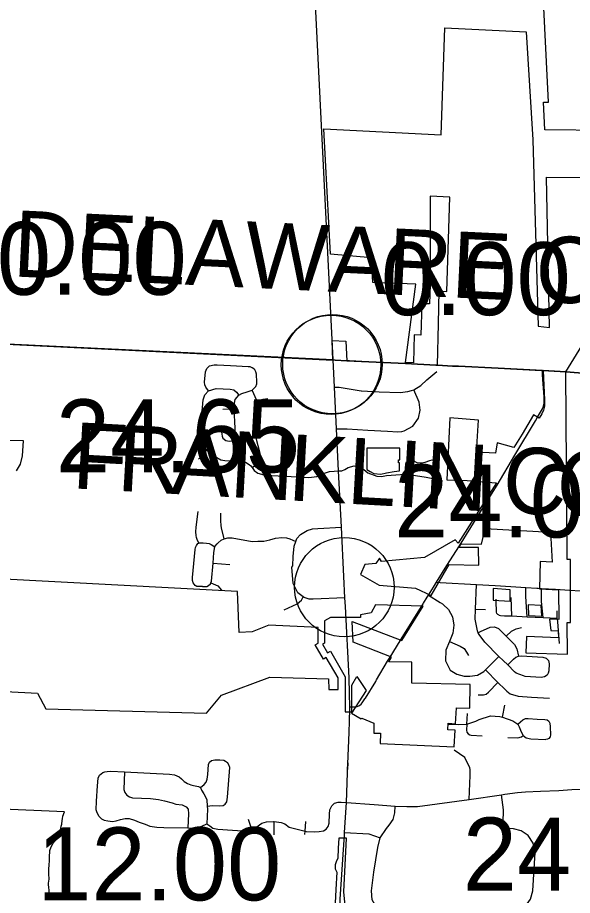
# Model space of a CAD drawing. Extents: x 1729596 to 1934326, y 644115 to 911751.
# Drawn here: x 1819179 to 1827541, y 770599 to 783844 of the extents above; entities that cross this region are included whole.
import ezdxf

# ---------------------------------------------------------------- set-up
doc = ezdxf.new("R2010")
doc.units = 0
for name, color, linetype in [('Default', 7, 'Continuous'), ('GM_X_Adjacent_County_Text', 7, 'Continuous'), ('GM_X_City_Street', 7, 'Continuous'), ('GM_X_Corporation', 7, 'Continuous'), ('GM_X_County', 7, 'Continuous'), ('GM_X_County_Road', 7, 'Continuous'), ('GM_X_Township_Road', 7, 'Continuous'), ('GM_X_US_Route', 7, 'Continuous')]:
    doc.layers.add(name, color=color, linetype=linetype)

msp = doc.modelspace()

# ---------------------------------------------------------------- linework, layer by layer
at = {"layer": 'Default'}
for centre in [(1823904, 778604), (1823904, 778604), (1823925, 778615), (1824103, 775250)]:
    msp.add_circle(centre, 750, dxfattribs=at)
at = {"layer": 'GM_X_City_Street'}
for points in [[(1827440, 778500), (1827802, 779087), (1828113, 779577), (1828183, 779692), (1828216, 779780), (1828313, 780101), (1828381, 780311), (1828487, 780643), (1828494, 780666)], [(1823936, 778682), (1823966, 778677), (1824141, 778666), (1824146, 778666)], [(1823936, 778682), (1823966, 778677), (1824145, 778671)], [(1822056, 778210), (1822017, 778267), (1821999, 778304), (1821997, 778344), (1822012, 778499), (1822031, 778551), (1822071, 778589), (1822141, 778605), (1822189, 778603), (1822388, 778593), (1822653, 778580), (1822678, 778578), (1822720, 778561)], [(1822459, 777154), (1822464, 777254), (1822464, 777456), (1822465, 777499), (1822458, 777648), (1822445, 777941), (1822443, 777995), (1822460, 778079), (1822513, 778146), (1822561, 778171), (1822637, 778197), (1822717, 778224), (1822770, 778277), (1822785, 778317), (1822786, 778344), (1822778, 778462), (1822771, 778498), (1822754, 778530), (1822720, 778561)], [(1824146, 778666), (1825025, 778622), (1825481, 778599), (1825506, 778597), (1825514, 778597)], [(1825505, 778597), (1825506, 778597), (1825736, 778586), (1825825, 778586), (1826422, 778555), (1827074, 778521)], [(1825514, 778597), (1825736, 778586), (1825825, 778586), (1826422, 778555), (1827092, 778520)], [(1824361, 778210), (1824631, 778199), (1824945, 778189), (1825060, 778201), (1825118, 778217), (1825151, 778228), (1825258, 778295), (1825347, 778377), (1825499, 778503)], [(1826983, 777761), (1827016, 777817), (1827089, 777940), (1827102, 777967), (1827111, 777999), (1827114, 778033), (1827114, 778068), (1827113, 778120), (1827100, 778318), (1827091, 778452), (1827091, 778494), (1827092, 778520)], [(1827074, 778521), (1827092, 778520), (1827440, 778500)], [(1827092, 778520), (1827440, 778500), (1827460, 778499)], [(1827440, 778500), (1827947, 778461), (1830173, 778324)], [(1827460, 778499), (1827947, 778461), (1830193, 778323)], [(1822030, 777316), (1821996, 777351), (1821952, 777420), (1821932, 777499), (1821933, 777562), (1821957, 777843), (1821975, 778075), (1822002, 778151), (1822056, 778210), (1822172, 778248), (1822383, 778239), (1822436, 778227), (1822477, 778194), (1822513, 778146)], [(1822716, 777056), (1822751, 777079), (1822801, 777116), (1822834, 777160), (1822843, 777198), (1822840, 777237), (1822833, 777267), (1822773, 777498), (1822769, 777583), (1822782, 777791), (1822794, 777953), (1822786, 778068), (1822717, 778224)], [(1823953, 778265), (1824024, 778269), (1824205, 778239), (1824356, 778210), (1824361, 778210)], [(1823985, 777638), (1824147, 777638), (1824458, 777620), (1824752, 777603), (1824912, 777595), (1824968, 777601), (1825006, 777608), (1825135, 777678), (1825221, 777798), (1825249, 777919), (1825232, 778042), (1825151, 778228)], [(1822786, 778068), (1822830, 778076), (1822876, 778087), (1822951, 778097)], [(1822273, 777933), (1822445, 777941)], [(1822253, 777594), (1822255, 777556), (1822260, 777526), (1822274, 777498), (1822318, 777462), (1822369, 777454), (1822464, 777456)], [(1821905, 777183), (1822030, 777316)], [(1822030, 777316), (1822105, 777249), (1822156, 777220)], [(1822156, 777220), (1822240, 777172), (1822304, 777161), (1822459, 777154), (1822535, 777147), (1822555, 777146), (1822616, 777134), (1822670, 777102), (1822692, 777082), (1822716, 777056), (1822747, 777008), (1822799, 776968), (1822889, 776943), (1823010, 776935), (1823496, 776909), (1823569, 776903), (1823690, 776921), (1823734, 776940), (1823773, 776959), (1823881, 776995), (1823951, 777001), (1824018, 777004)], [(1824018, 777004), (1824065, 777007), (1824109, 777025), (1824161, 777054), (1824251, 777080), (1824358, 777055), (1824400, 777025), (1824459, 776977), (1824592, 776923), (1824663, 776922), (1824740, 776933), (1825018, 776954), (1825175, 776934), (1825336, 776910), (1825435, 776889)], [(1825018, 776954), (1825031, 777112), (1825042, 777142), (1825065, 777164), (1825087, 777174), (1825110, 777175), (1825144, 777161), (1825168, 777146), (1825197, 777133), (1825274, 777125), (1825322, 777138), (1825390, 777163), (1825427, 777169), (1825464, 777164), (1825508, 777129), (1825524, 777096), (1825526, 777059), (1825519, 777020), (1825484, 776879)], [(1825435, 776889), (1825484, 776879), (1825584, 776853)], [(1821913, 775914), (1821888, 775969), (1821876, 776000), (1821869, 776029), (1821865, 776086), (1821868, 776154), (1821900, 776394)], [(1822295, 775980), (1822252, 776143), (1822245, 776179), (1822240, 776252), (1822243, 776366)], [(1824113, 775091), (1823635, 775067), (1823574, 775071), (1823496, 775095), (1823484, 775103), (1823404, 775164), (1823334, 775303), (1823314, 775554), (1823326, 775574), (1823334, 775711), (1823349, 775867), (1823374, 775941), (1823389, 775982), (1823445, 776047), (1823541, 776103), (1823626, 776131), (1823704, 776136), (1824060, 776153)], [(1821966, 775258), (1821883, 775258), (1821853, 775273), (1821838, 775294), (1821826, 775316), (1821815, 775353), (1821815, 775395), (1821853, 775817), (1821862, 775849), (1821876, 775881), (1821896, 775908), (1821913, 775914), (1821928, 775918), (1821976, 775917), (1822027, 775912), (1822064, 775907), (1822098, 775892), (1822152, 775856)], [(1821966, 775258), (1822029, 775262), (1822057, 775274), (1822085, 775300), (1822093, 775316), (1822104, 775339), (1822125, 775611), (1822138, 775775), (1822152, 775856), (1822153, 775862), (1822187, 775906), (1822200, 775917), (1822201, 775918)], [(1822201, 775918), (1822249, 775961), (1822290, 775979), (1822295, 775980), (1822347, 775993), (1822415, 775993), (1822715, 775941), (1822802, 775943), (1822891, 775946), (1822982, 775965), (1823068, 775990), (1823161, 776001), (1823234, 775995), (1823282, 775981), (1823374, 775941)], [(1822125, 775611), (1822379, 775591)], [(1822093, 775316), (1822198, 775270), (1822253, 775203)], [(1825495, 775326), (1825549, 775321), (1826095, 775288), (1826379, 775273), (1826611, 775259), (1826837, 775246), (1827003, 775237), (1827023, 775235)], [(1826802, 773912), (1826692, 773954), (1826668, 773975), (1826566, 774077), (1826497, 774144), (1826434, 774206), (1826220, 774418), (1826134, 774536), (1826121, 774563), (1826109, 774591), (1826076, 774769), (1826083, 774917), (1826095, 775288)], [(1826858, 774804), (1826848, 774951), (1826840, 775111), (1826837, 775246)], [(1827099, 774790), (1827075, 775036), (1827076, 775232)], [(1823197, 774908), (1823394, 774998), (1823460, 775055), (1823484, 775103)], [(1825296, 775010), (1825353, 775100)], [(1825373, 775131), (1825548, 775021), (1825581, 774998), (1825593, 774987)], [(1826628, 774818), (1826617, 775093)], [(1827498, 775207), (1827662, 775197), (1828600, 775146), (1828663, 775145), (1828778, 775136), (1829364, 775096), (1829531, 775087), (1830387, 775031), (1831077, 774994), (1831207, 774985), (1832172, 774932), (1832553, 774913), (1832991, 774890), (1833285, 774873), (1833579, 774858), (1833879, 774836), (1833947, 774835), (1833997, 774825), (1834053, 774805), (1834088, 774789), (1834140, 774757), (1834272, 774660), (1834319, 774634)], [(1825593, 774987), (1825674, 774913), (1825734, 774802), (1825756, 774679), (1825740, 774556), (1825691, 774428), (1825635, 774300), (1825627, 774140), (1825701, 773998), (1825797, 773936), (1825908, 773909), (1825995, 773905), (1826109, 773922), (1826207, 773979), (1826232, 774002), (1826434, 774206)], [(1826435, 774829), (1826416, 774836), (1826401, 774853), (1826396, 774871), (1826395, 774911), (1826393, 774998), (1826391, 775067)], [(1826083, 774917), (1826229, 774912)], [(1826435, 774829), (1826458, 774824), (1826516, 774818), (1826628, 774818), (1826858, 774804), (1827099, 774790), (1827311, 774780)], [(1827323, 774727), (1827323, 774736), (1827311, 774780), (1827313, 774834), (1827310, 774891)], [(1827349, 774398), (1827323, 774727)], [(1826121, 774563), (1826158, 774582), (1826301, 774645), (1826366, 774653), (1826425, 774625), (1826545, 774510), (1826669, 774386), (1826704, 774322), (1826727, 774209)], [(1826545, 774510), (1826622, 774587), (1826693, 774621), (1826775, 774640)], [(1824792, 774194), (1824943, 774438), (1824960, 774466)], [(1825691, 774428), (1825851, 774360), (1825908, 774324), (1825946, 774268), (1825976, 774220)], [(1826566, 774077), (1826653, 774166), (1826687, 774193), (1826727, 774209), (1826772, 774213), (1827096, 774194), (1827145, 774180), (1827180, 774142), (1827190, 774092), (1827185, 773986), (1827178, 773952), (1827160, 773923)], [(1826232, 774002), (1826419, 773811), (1826523, 773711), (1826552, 773682), (1826605, 773642), (1826725, 773604), (1826925, 773592), (1827194, 773577)], [(1827160, 773923), (1827119, 773896), (1827071, 773889), (1826828, 773903), (1826802, 773912)], [(1824420, 773573), (1824421, 773575), (1824576, 773829), (1824582, 773839), (1824583, 773841)], [(1826119, 773628), (1826202, 773628), (1826242, 773638), (1826274, 773665), (1826419, 773811)], [(1824241, 773445), (1824265, 773445), (1824298, 773448), (1824324, 773460), (1824355, 773485), (1824357, 773487)], [(1826486, 773291), (1826525, 773472)], [(1825670, 773185), (1825820, 773176), (1825950, 773184), (1825996, 773196), (1826084, 773229), (1826134, 773255), (1826307, 773307), (1826445, 773298), (1826486, 773291), (1826641, 773232), (1826717, 773181), (1826737, 773144), (1826767, 773067), (1826797, 773010), (1826846, 772978), (1826915, 772963), (1827142, 772952)], [(1825950, 773184), (1825960, 773342)], [(1826717, 773181), (1826757, 773218), (1826794, 773249), (1826832, 773266), (1826874, 773269), (1827008, 773260), (1827128, 773254), (1827160, 773246), (1827185, 773227), (1827199, 773198), (1827205, 773143), (1827211, 773023), (1827204, 772993), (1827187, 772969), (1827166, 772956), (1827142, 772952)], [(1825950, 773184), (1825945, 773090), (1825952, 773061), (1825970, 773036), (1825996, 773021), (1826014, 773018), (1826181, 773007)], [(1826566, 772981), (1826721, 772975), (1826774, 772992), (1826797, 773010)], [(1825983, 772046), (1825999, 772408), (1826001, 772438), (1826001, 772498), (1825996, 772523), (1825922, 772681), (1825761, 772791)], [(1821936, 772229), (1821990, 772275), (1822020, 772310), (1822038, 772355), (1822047, 772422), (1822056, 772574), (1822072, 772610), (1822104, 772635), (1822154, 772645), (1822229, 772644), (1822288, 772638), (1822315, 772627), (1822341, 772604)], [(1822037, 771947), (1822119, 771954), (1822222, 771949), (1822279, 771954), (1822309, 771978), (1822334, 772011), (1822342, 772080), (1822377, 772528), (1822362, 772570), (1822341, 772604)], [(1820406, 771790), (1820378, 771847), (1820361, 771892), (1820368, 772023), (1820384, 772253), (1820393, 772369), (1820415, 772414), (1820464, 772453)], [(1820464, 772453), (1820492, 772463), (1820529, 772470), (1820583, 772472), (1820792, 772462), (1821467, 772429), (1821543, 772419), (1821614, 772390), (1821650, 772357), (1821690, 772320), (1821742, 772286), (1821790, 772268), (1821830, 772257), (1821907, 772243), (1821936, 772229), (1821952, 772186), (1821987, 772131), (1822009, 772087), (1822031, 772040), (1822037, 771947), (1822039, 771901), (1822032, 771679)], [(1820792, 772462), (1820781, 772195), (1820796, 772150), (1820826, 772112), (1820866, 772089), (1820913, 772073), (1821180, 772064), (1821302, 772045), (1821395, 772025), (1821510, 771996), (1821566, 771977), (1821660, 771966), (1821721, 771937), (1821748, 771901), (1821757, 771828), (1821747, 771618)], [(1826525, 772125), (1826714, 772151), (1826836, 772161), (1827059, 772170), (1827337, 772184), (1827532, 772195), (1827691, 772201), (1828033, 772218), (1828183, 772224), (1828323, 772224), (1828435, 772215), (1828494, 772212), (1828931, 772182), (1829307, 772160), (1829765, 772135), (1829929, 772122)], [(1824135, 772002), (1824551, 771970), (1824871, 771948), (1825045, 771940), (1825204, 771941), (1825983, 772046), (1826472, 772117), (1826525, 772125)], [(1826492, 771616), (1826504, 771852), (1826502, 771888), (1826472, 772117)], [(1822032, 771679), (1822074, 771650), (1822123, 771615), (1822197, 771601), (1822638, 771569), (1822714, 771577), (1822771, 771622), (1822860, 771691), (1822929, 771707), (1823035, 771715), (1823046, 771714), (1823151, 771697), (1823206, 771680), (1823271, 771631), (1823513, 771567), (1823526, 771564), (1823659, 771561), (1823724, 771563), (1823792, 771576), (1823832, 771598), (1823860, 771639), (1823875, 771688), (1823879, 771823), (1823887, 771892), (1823913, 771949), (1823955, 771990), (1824010, 772008), (1824057, 772005), (1824135, 772002)], [(1824644, 770369), (1824587, 770417), (1824524, 770534), (1824512, 770667), (1824546, 770950), (1824608, 771322), (1824643, 771469), (1824738, 771611), (1824779, 771657), (1824839, 771744), (1824865, 771846), (1824871, 771948)], [(1820406, 771790), (1820446, 771755), (1820483, 771736), (1820541, 771727), (1820611, 771712), (1820665, 771727), (1820728, 771746), (1820798, 771762), (1820862, 771759), (1820939, 771736), (1821011, 771704), (1821102, 771676), (1821172, 771643), (1821279, 771631), (1821385, 771623), (1821747, 771618), (1821837, 771616), (1821899, 771625), (1821956, 771644), (1822032, 771679)], [(1822714, 771577), (1822658, 771747)], [(1823047, 771513), (1823046, 771714)], [(1823509, 771520), (1823513, 771567), (1823525, 771712)], [(1824106, 771550), (1824475, 771530), (1824643, 771469)], [(1826832, 770435), (1826910, 770542), (1826947, 770669), (1826978, 771246), (1826951, 771386), (1826872, 771504), (1826771, 771573), (1826654, 771605), (1826555, 771611), (1826492, 771616)]]:
    msp.add_lwpolyline(points, dxfattribs=at)
at = {"layer": 'GM_X_Corporation'}
for points in [[(1829006, 782129), (1827128, 782148), (1827107, 782565), (1827182, 782566), (1827094, 784298)], [(1818182, 778957), (1823932, 778674), (1823918, 778971), (1824127, 778960), (1824141, 778666), (1825025, 778622), (1825481, 778599), (1825506, 778597), (1825523, 779224), (1825533, 779720), (1825651, 779713), (1825692, 781132), (1825397, 781147), (1825395, 779815), (1825387, 779525), (1825271, 779527), (1825258, 779053), (1825157, 779059), (1825145, 778634), (1825026, 778639), (1825182, 779821), (1824534, 779849), (1824515, 780220), (1823897, 780274), (1823795, 782165), (1825564, 782072), (1825620, 783690), (1826843, 783626), (1826946, 782000), (1827027, 779186), (1827198, 779170), (1827151, 781435), (1828757, 781433)], [(1819165, 777003), (1819223, 777108), (1819253, 777229), (1819268, 777456), (1818703, 777466)], [(1818508, 773703), (1819478, 773652), (1819605, 773412), (1822027, 773351), (1822253, 773619), (1822982, 773891), (1823867, 773865), (1823869, 773706), (1824013, 773704), (1824009, 773883), (1823832, 774190), (1823788, 774165), (1823663, 774381), (1823707, 774406), (1823707, 774642), (1822967, 774677), (1822717, 774575), (1822517, 774567), (1822492, 775187), (1818880, 775374)], [(1819656, 770583), (1819656, 770666), (1819650, 770728), (1819647, 770756), (1819647, 770786), (1819650, 770814), (1819656, 770842), (1819656, 770870), (1819650, 770898), (1819650, 770984), (1819650, 771015), (1819653, 771043), (1819656, 771074), (1819662, 771108), (1819662, 771166), (1819659, 771194), (1819665, 771250), (1819665, 771278), (1819684, 771333), (1819714, 771389), (1819742, 771417), (1819767, 771445), (1819779, 771472), (1819795, 771500), (1819807, 771528), (1819820, 771584), (1819829, 771611), (1819838, 771645), (1819844, 771673), (1819850, 771729), (1819857, 771757), (1819863, 771794), (1819885, 771859), (1818834, 771906)], [(1824115, 770445), (1824097, 770653), (1824134, 771461), (1824020, 771463), (1824012, 771314), (1824004, 771157), (1823985, 771119), (1823963, 771063), (1823967, 770998), (1823992, 770950), (1823977, 770688), (1823965, 770484)]]:
    msp.add_lwpolyline(points, dxfattribs=at)
for points in [[(1824345, 775442), (1824627, 775281), (1825175, 775235), (1825413, 775126), (1825685, 775591), (1826129, 775580), (1826126, 775849), (1825830, 775846), (1825867, 775906), (1826173, 775897), (1826228, 776137), (1827210, 776079), (1827238, 775627), (1827055, 775635), (1827043, 775226), (1827330, 775211), (1827337, 774761), (1827196, 774766), (1827218, 774598), (1827327, 774593), (1827332, 774484), (1826851, 774504), (1826841, 774261), (1827466, 774237), (1827464, 774716), (1827514, 774716), (1827510, 775666), (1827460, 775665), (1827440, 778500), (1827098, 778520), (1827121, 778076), (1827120, 777980), (1827107, 777918), (1827081, 777867), (1827042, 777801), (1826956, 777852), (1826782, 777559), (1826660, 777355), (1826409, 777430), (1826380, 777271), (1826098, 777288), (1826124, 777772), (1825694, 777807), (1825650, 776871), (1826109, 776852), (1826109, 776842), (1826395, 776822), (1825819, 775914), (1825776, 775965), (1825313, 775697), (1824665, 775637), (1824635, 775689), (1824578, 775607), (1824414, 775592)], [(1824442, 777348), (1824442, 777026), (1824494, 776994), (1824548, 776966), (1824656, 776953), (1824740, 776974), (1824853, 776996), (1824934, 777003), (1824934, 777124), (1824922, 777124), (1824922, 777172), (1824942, 777172), (1824942, 777248), (1824942, 777348)], [(1826345, 775056), (1826603, 775041), (1826601, 775212), (1826347, 775231)], [(1823775, 774388), (1823850, 774258), (1823893, 774283), (1824116, 773897), (1824117, 773370), (1824217, 773370), (1824216, 773770), (1824292, 773900), (1824434, 773692), (1824210, 773349), (1824358, 773262), (1824368, 773274), (1824549, 773200), (1824547, 773047), (1824647, 773046), (1824645, 772890), (1825759, 772839), (1825774, 773090), (1825665, 773097), (1825671, 773197), (1825780, 773190), (1825795, 773428), (1825995, 773423), (1825999, 773780), (1825120, 773801), (1825121, 774119), (1824773, 774122), (1824817, 774196), (1824236, 774422), (1824220, 774734), (1824970, 774444), (1825290, 774965), (1824574, 774985), (1824507, 774863), (1824348, 774835), (1824349, 774792), (1823893, 774792), (1823807, 774742), (1823807, 774406)], [(1826873, 774982), (1826880, 774820), (1827079, 774810), (1827071, 774971)]]:
    msp.add_lwpolyline(points, close=True, dxfattribs=at)
at = {"layer": 'GM_X_County'}
for points in [[(1811853, 779256), (1817214, 778979), (1817250, 778977), (1818151, 778958), (1818187, 778957), (1823936, 778682), (1823966, 778677), (1824141, 778666), (1825025, 778622), (1825481, 778599), (1825506, 778597), (1825736, 778586), (1825825, 778586), (1826422, 778555), (1827092, 778520), (1827440, 778500), (1827947, 778461)], [(1827947, 778461), (1827440, 778500), (1827092, 778520), (1826422, 778555), (1825825, 778586), (1825736, 778586), (1825506, 778597), (1825481, 778599), (1825025, 778622), (1824141, 778666), (1823966, 778677), (1823936, 778682), (1818187, 778957), (1818151, 778958), (1817250, 778977), (1817214, 778979), (1811853, 779256)]]:
    msp.add_lwpolyline(points, dxfattribs=at)
at = {"layer": 'GM_X_County_Road'}
for points in [[(1825353, 775100), (1825373, 775131), (1825449, 775251), (1825495, 775326), (1825646, 775575), (1825837, 775875), (1826221, 776491), (1826407, 776790), (1826673, 777239), (1826983, 777761)], [(1827023, 775235), (1827076, 775232), (1827287, 775220), (1827498, 775207)], [(1824960, 774466), (1825290, 774999), (1825296, 775010)], [(1824589, 773850), (1824756, 774135), (1824792, 774194)], [(1824583, 773841), (1824588, 773850), (1824589, 773850)], [(1824357, 773487), (1824374, 773504), (1824415, 773565), (1824420, 773572), (1824420, 773573)], [(1824188, 773445), (1824241, 773445)]]:
    msp.add_lwpolyline(points, dxfattribs=at)
at = {"layer": 'GM_X_Township_Road'}
msp.add_lwpolyline([(1824145, 778671), (1824181, 778670), (1825025, 778622), (1825481, 778599), (1825505, 778597)], dxfattribs=at)
at = {"layer": 'GM_X_US_Route'}
for points in [[(1823936, 778682), (1823645, 784547), (1823597, 785555), (1823580, 785831), (1823563, 786025)], [(1824097, 775409), (1824060, 776153), (1824018, 777004), (1823985, 777638), (1823953, 778265), (1823936, 778682)], [(1824119, 774956), (1824113, 775091), (1824097, 775409)], [(1824182, 773646), (1824175, 773880), (1824119, 774956)], [(1824176, 773086), (1824181, 773197), (1824188, 773445), (1824182, 773646)], [(1824154, 772583), (1824174, 773056), (1824176, 773086)], [(1824104, 771515), (1824106, 771550), (1824135, 772002), (1824154, 772602), (1824151, 772498), (1824154, 772583)], [(1823997, 769664), (1824001, 769752), (1824017, 770059), (1824036, 770410), (1824042, 770542), (1824104, 771515)]]:
    msp.add_lwpolyline(points, dxfattribs=at)

# ---------------------------------------------------------------- texts
at = {"layer": 'Default'}
for s, p in [('0.00', (1818866, 779661)), ('0.00', (1824654, 779354)), ('24.65', (1819756, 776983)), ('24.00', (1824853, 776000)), ('24.00', (1825889, 770673)), ('12.00', (1819473, 770525))]:
    msp.add_text(s, height=1100, dxfattribs=at).set_placement(p)
at = {"layer": 'GM_X_Adjacent_County_Text'}
for s, rotation, p in [('DELAWARE COUNTY', 357.2562, (1819097, 779939)), ('F', 356.8079, (1819990, 776742)), ('R', 356.8077, (1820666, 776705)), ('A', 356.8076, (1821479, 776659)), ('N', 356.8079, (1822362, 776610)), ('K', 356.8079, (1823245, 776561)), ('L', 356.8078, (1824128, 776511)), ('I', 356.8075, (1824875, 776470)), ('N', 356.8076, (1825284, 776447)), ('C', 356.8078, (1826470, 776381)), ('O', 356.8074, (1827283, 776336))]:
    msp.add_text(s, height=1000, rotation=rotation, dxfattribs=at).set_placement(p)

doc.saveas('drawing.dxf')
